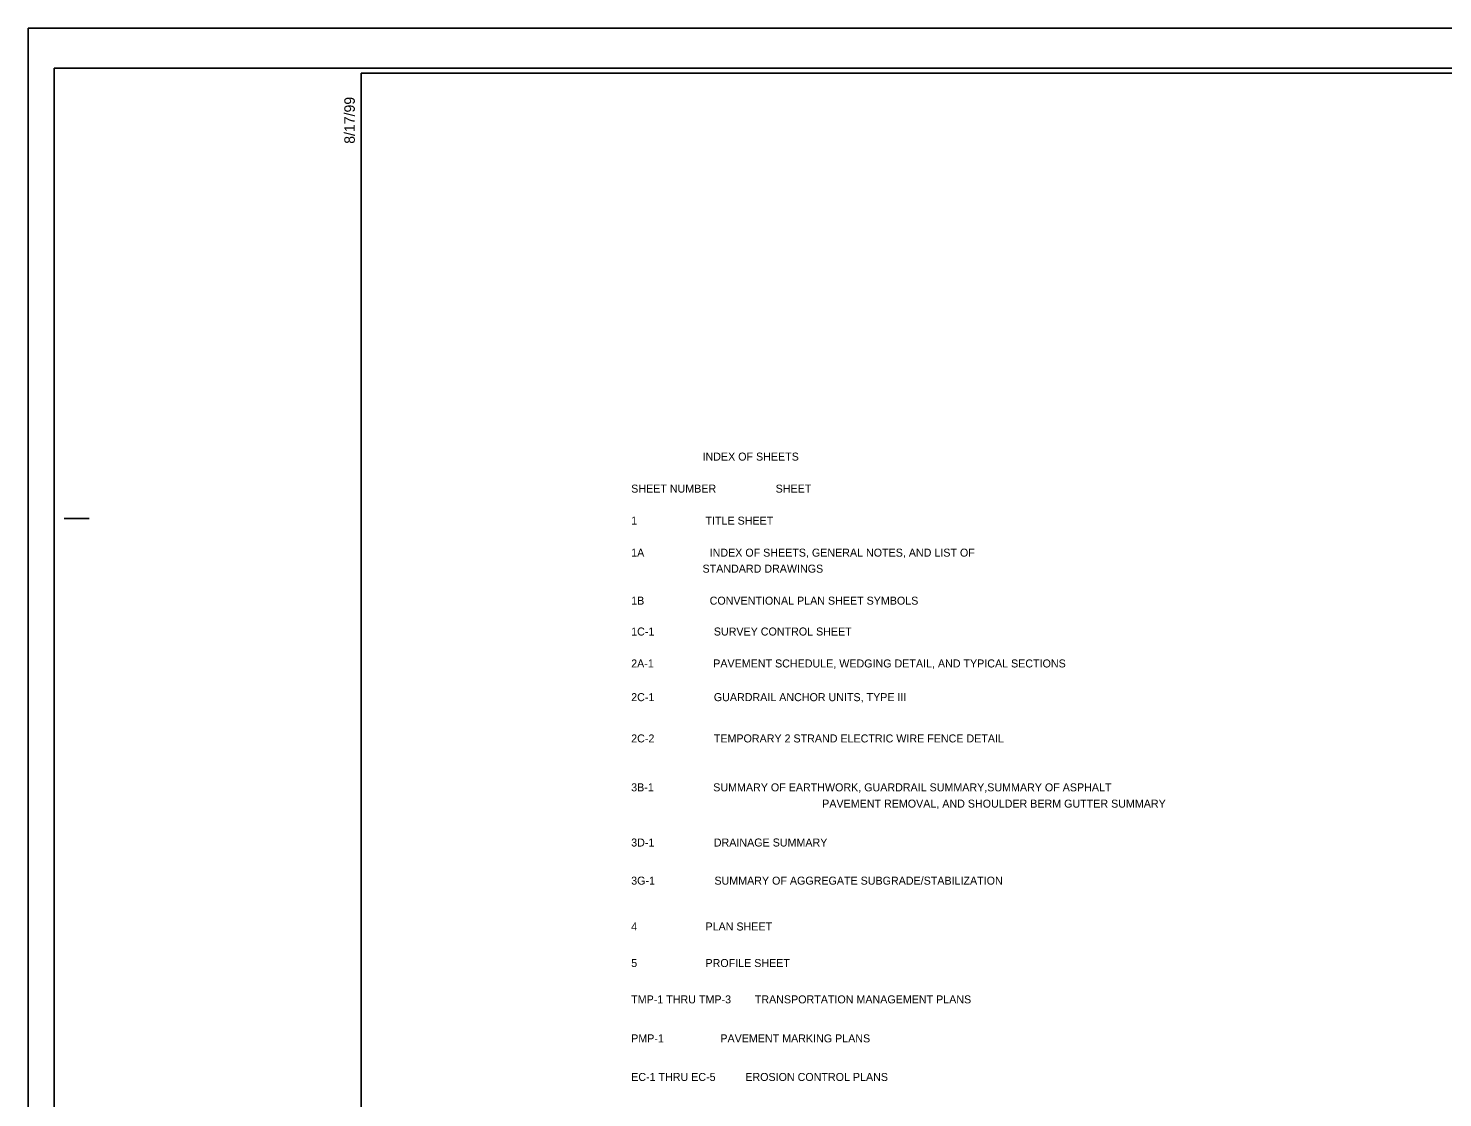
# Model space of a CAD drawing. Extents: x 1974126 to 1975810, y 438878 to 442173.
# Drawn here: x 1974126 to 1974833, y 441639 to 442173 of the extents above; entities that cross this region are included whole.
import ezdxf

# ---------------------------------------------------------------- set-up
doc = ezdxf.new("R2010")
doc.units = 0
for name, color, linetype in [('Sheet Cutting Line CELL', 7, 'Continuous'), ('Sheet Data Text CELL', 7, 'Continuous'), ('Sheet Plan CELL', 7, 'Continuous'), ('Sheet Plot Border Inside CELL', 7, 'Continuous'), ('Sheet Plot Border Outside CELL', 7, 'Continuous')]:
    doc.layers.add(name, color=color, linetype=linetype)

msp = doc.modelspace()

# ---------------------------------------------------------------- linework, layer by layer
at = {"layer": 'Sheet Cutting Line CELL'}
for p, q in [((1975809.14, 442173.29), (1974125.64, 442173.29)), ((1974125.64, 442173.29), (1974125.64, 441078.29))]:
    msp.add_line(p, q, dxfattribs=at)
at = {"layer": 'Sheet Plan CELL'}
for p, q in [((1974292.14, 442150.79), (1974292.14, 442150.79)), ((1974143.64, 441928.29), (1974156.14, 441928.29))]:
    msp.add_line(p, q, dxfattribs=at)
msp.add_lwpolyline([(1975792.14, 442150.79), (1974292.14, 442150.79), (1974292.14, 441100.79), (1975792.14, 441100.79)], close=True, dxfattribs=at)
at = {"layer": 'Sheet Plot Border Inside CELL'}
msp.add_lwpolyline([(1974138.64, 441098.29), (1975804.64, 441098.29), (1975804.64, 442153.29), (1974138.64, 442153.29)], close=True, dxfattribs=at)
at = {"layer": 'Sheet Plot Border Outside CELL'}
msp.add_lwpolyline([(1974125.64, 441078.29), (1975809.14, 441078.29), (1975809.14, 442173.29), (1974125.64, 442173.29)], close=True, dxfattribs=at)

# ---------------------------------------------------------------- texts
at = {"layer": 'Sheet Data Text CELL'}
for s, p in [('                        INDEX OF SHEETS ', (1974427.08, 441957.25)), ('SHEET NUMBER                    SHEET   ', (1974427.08, 441941.25)), ('1                       TITLE SHEET', (1974427.08, 441925.25)), ('1A                      INDEX OF SHEETS, GENERAL NOTES, AND LIST OF ', (1974427.08, 441909.25)), ('                        STANDARD DRAWINGS', (1974427.08, 441901.25)), ('1B                      CONVENTIONAL PLAN SHEET SYMBOLS ', (1974427.08, 441885.25)), ('1C-1                    SURVEY CONTROL SHEET', (1974427.08, 441869.83)), ('2A-1                    PAVEMENT SCHEDULE, WEDGING DETAIL, AND TYPICAL SECTIONS', (1974427.08, 441853.87)), ('2C-1                    GUARDRAIL ANCHOR UNITS, TYPE III', (1974427.08, 441837.03)), ('2C-2                    TEMPORARY 2 STRAND ELECTRIC WIRE FENCE DETAIL', (1974427.08, 441816.4)), ('3B-1                    SUMMARY OF EARTHWORK, GUARDRAIL SUMMARY,SUMMARY OF ASPHALT', (1974427.08, 441791.95)), ('PAVEMENT REMOVAL, AND SHOULDER BERM GUTTER SUMMARY', (1974522.58, 441783.82)), ('3D-1                    DRAINAGE SUMMARY', (1974427.08, 441764.38)), ('3G-1                    SUMMARY OF AGGREGATE SUBGRADE/STABILIZATION', (1974427.08, 441745.33)), ('4                       PLAN SHEET', (1974427.08, 441722.42)), ('5                       PROFILE SHEET', (1974427.08, 441704.16)), ('TMP-1 THRU TMP-3        TRANSPORTATION MANAGEMENT PLANS', (1974427.08, 441685.99)), ('PMP-1                   PAVEMENT MARKING PLANS', (1974427.08, 441666.5)), ('EC-1 THRU EC-5          EROSION CONTROL PLANS', (1974427.08, 441647.22))]:
    msp.add_text(s, height=4, dxfattribs=at).set_placement(p)
at = {"layer": 'Sheet Plan CELL'}
msp.add_text('8/17/99', height=5.25, rotation=90, dxfattribs=at).set_placement((1974288.89, 442115.59))

doc.saveas('drawing.dxf')
